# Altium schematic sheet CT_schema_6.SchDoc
size 403 x 220 mm
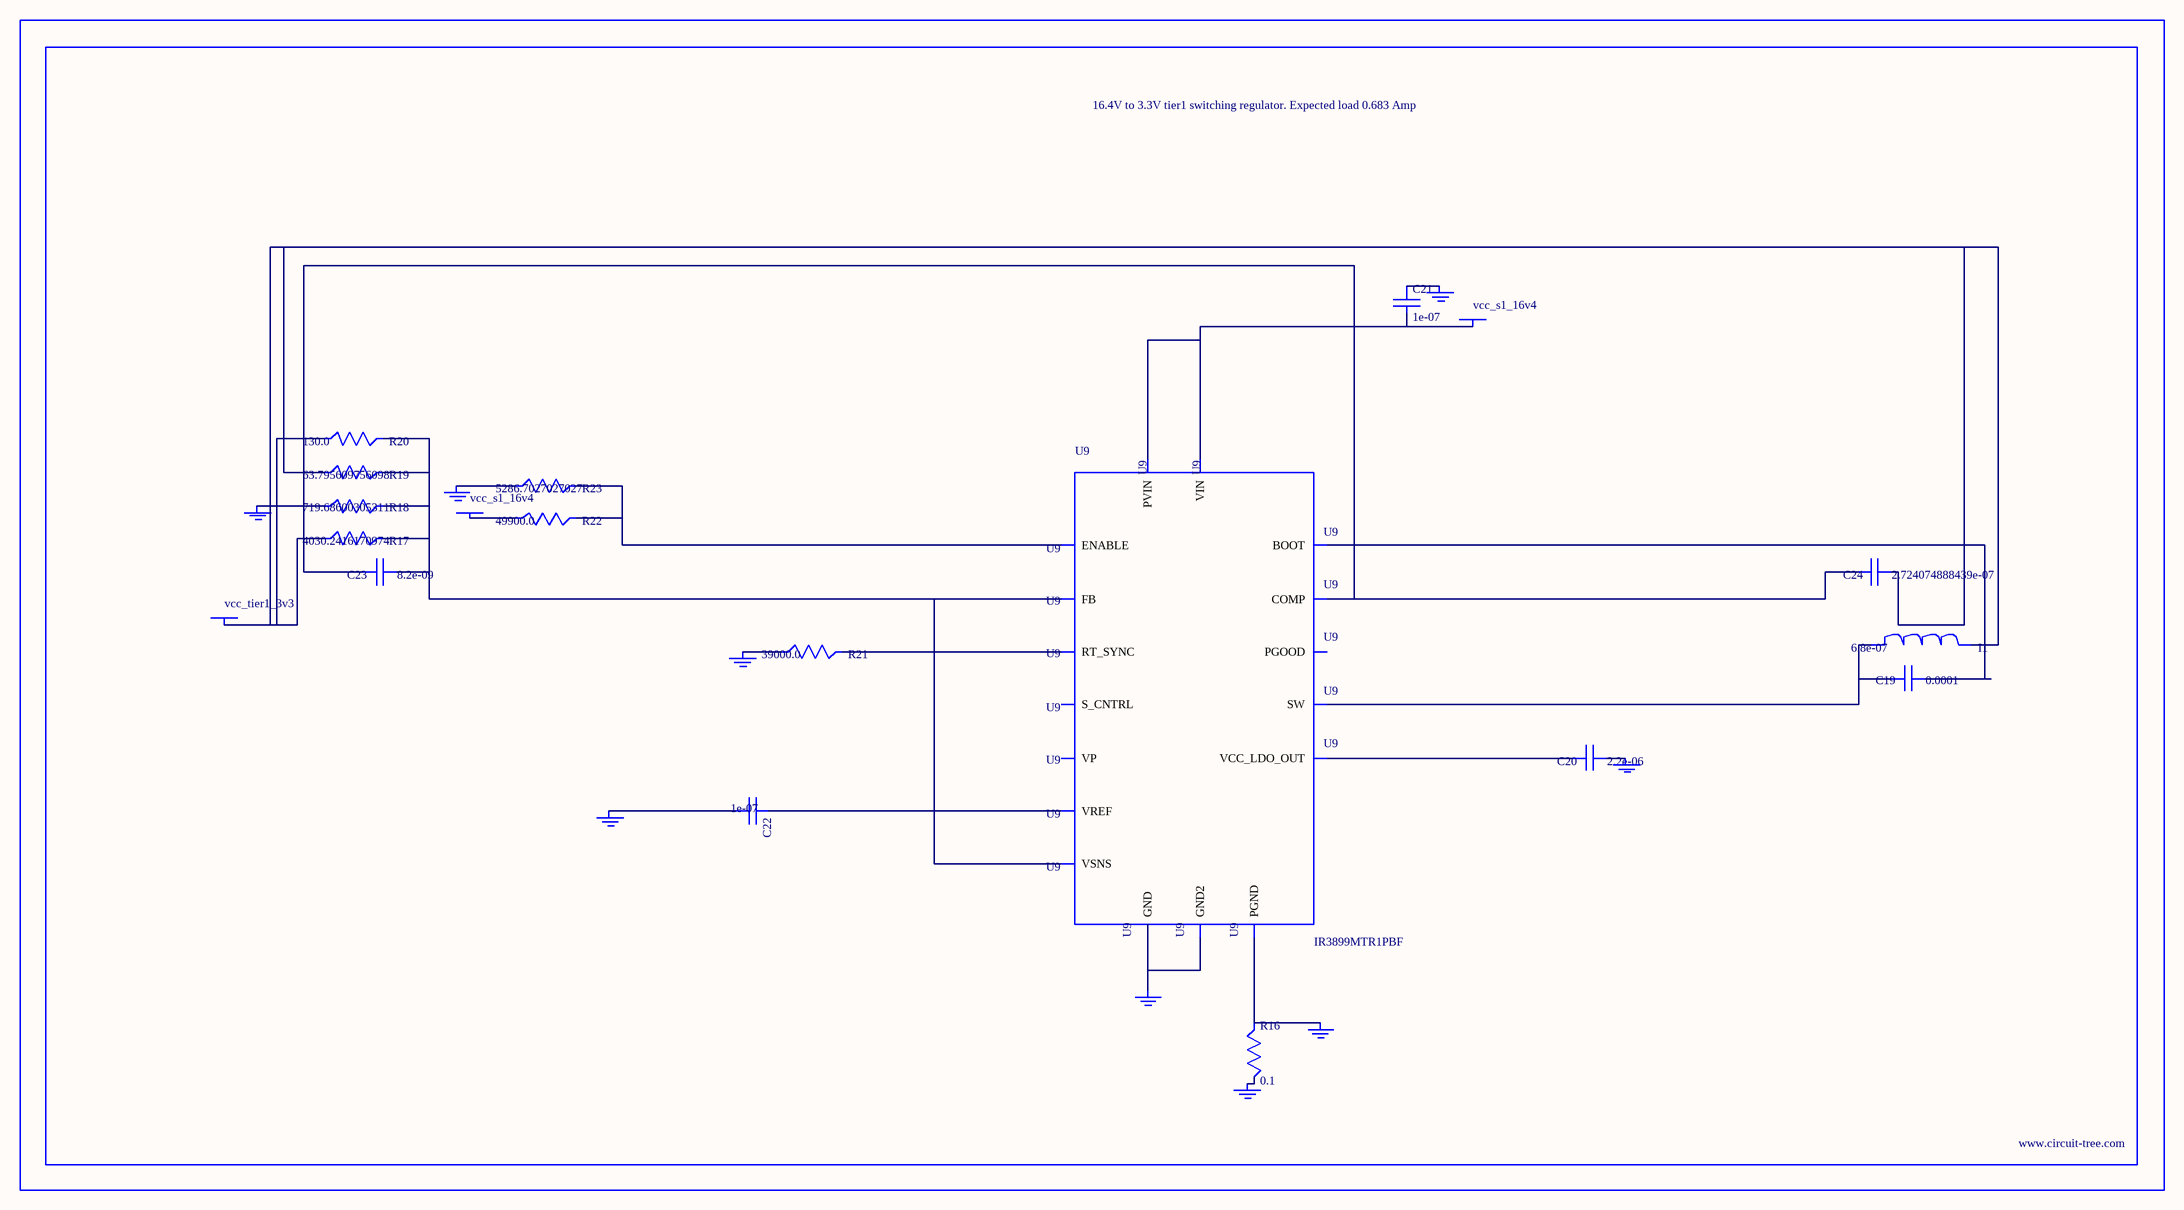
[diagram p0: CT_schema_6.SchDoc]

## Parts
BORDER5  (no value)
C19  0.0001  [C1210]
C20  2.2e-06  [C0603]
C21  1e-07  [C0402]
C22  1e-07  [C0402]
C23  8.2e-09  [C0402]
C24  2.724074888439e-07  [R0603]
GND_INSTANCE_5_0  (no value)
GND_INSTANCE_5_1  (no value)
GND_INSTANCE_5_2  (no value)
GND_INSTANCE_5_3  (no value)
GND_INSTANCE_5_4  (no value)
GND_INSTANCE_5_5  (no value)
GND_INSTANCE_5_6  (no value)
GND_INSTANCE_5_7  (no value)
GND_INSTANCE_5_8  (no value)
I1  6.8e-07  [IND25X25CZ]
POWER_INSTANCE_5_0  vcc_s1_16v4
POWER_INSTANCE_5_1  vcc_s1_16v4
POWER_INSTANCE_5_2  vcc_tier1_3v3
R16  0.1  [R0603]
R17  4030.2416170974  [R0603]
R18  719.68600305311  [R0603]
R19  63.795609756098  [R0603]
R20  130.0  [R0603]
R21  39000.0  [R0603]
R22  49900.0  [R0603]
R23  5286.7027027027  [R0603]
U9  IR3899MTR1PBF  [IR3899MTR1PBF]

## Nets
NetC19_1: C19.1 U9.14(BOOT)
NetC19_2: C19.2 I1.1 U9.12(SW)
NetC20_1: C20.1 GND_INSTANCE_5_4.0(GND)
NetC20_2: C20.2 U9.10(VCC_LDO_OUT)
NetC21_1: C21.1 GND_INSTANCE_5_3.0(GND)
NetC21_2: C21.2 POWER_INSTANCE_5_0.0(PWR) U9.9(VIN) U9.13(PVIN)
NetC22_1: C22.1 U9.2(VREF)
NetC22_2: C22.2 GND_INSTANCE_5_1.0(GND)
NetC23_1: C23.1 R17.2 R18.2 R19.2 R20.2 U9.1(FB) U9.8(VSNS)
NetC23_2: C23.2 C24.2 U9.3(COMP)
NetC24_1: C24.1 I1.2 POWER_INSTANCE_5_2.0(PWR) R17.1 R19.1 R20.1
NetGND_INSTANCE_5_0_0: GND_INSTANCE_5_0.0(GND) R18.1
NetGND_INSTANCE_5_2_0: GND_INSTANCE_5_2.0(GND) R21.1
NetGND_INSTANCE_5_5_0: GND_INSTANCE_5_5.0(GND) R16.2
NetGND_INSTANCE_5_6_0: GND_INSTANCE_5_6.0(GND) R16.1 U9.11(PGND)
NetGND_INSTANCE_5_7_0: GND_INSTANCE_5_7.0(GND) R23.1
NetGND_INSTANCE_5_8_0: GND_INSTANCE_5_8.0(GND) U9.4(GND) U9.17(GND2)
NetPOWER_INSTANCE_5_1_0: POWER_INSTANCE_5_1.0(PWR) R22.1
NetR21_2: R21.2 U9.5(RT_SYNC)
NetR22_2: R22.2 R23.2 U9.15(ENABLE)

Not connected (* = marked no-connect by the designer): U9 6(S_CNTRL) 7(PGOOD) 16(VP)

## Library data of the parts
BORDER5 = BORDER_PAGE5
C19 = GRM32ER61A107ME20L
C20 = C0603C225K8RACTU
C21 C22 = C0402C104K3RACTU
C23 = C0402C822K3RAC
C24 = C24
GND_INSTANCE_5_0-GND_INSTANCE_5_8 = GND
I1 = IHLP2525CZERR68M01
POWER_INSTANCE_5_0-POWER_INSTANCE_5_2 = PWR
R16 = ERJ-3RSFR10V
R17 = R17
R18 = R18
R19 = R19
R20 = RC0603JR-07130RL
R21 = RC0603JR-0739KL
R22 = RC0603FR-0749K9
R23 = R23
